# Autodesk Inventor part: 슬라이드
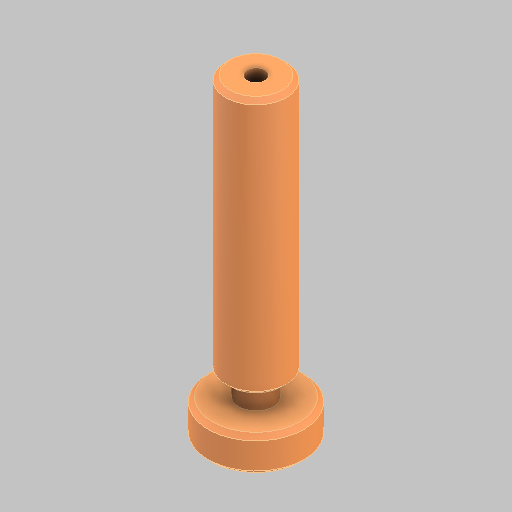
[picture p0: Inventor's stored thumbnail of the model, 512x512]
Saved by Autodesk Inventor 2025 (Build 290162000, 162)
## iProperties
Created: 2024-07
Part Number: 슬라이드
Material: 강철, 연강
Document SubType Name: Modeling
Designer: 현기
Density: 7.86 g/cm^3
Appearance: 기본값
Author: jhkim
Sending System: Autodesk Inventor 2025
Preprocessor: ST-DEVELOPER v20
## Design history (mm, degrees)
feature "솔리드1"
node "솔리드2"
